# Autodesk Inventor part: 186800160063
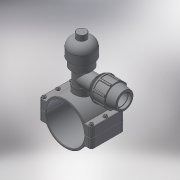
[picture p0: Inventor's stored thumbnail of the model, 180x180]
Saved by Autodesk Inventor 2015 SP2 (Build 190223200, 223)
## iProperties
Created: 2017-05
Part Number: 186800160063
Material: Generic
Description: PLASSON MECHANICAL TAPPING VALVE 160-63
Document SubType Name: Modeling
Designer: KIM
Density: 1 g/cm^3
Appearance: Default
Author: KIM
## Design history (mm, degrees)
derived "18680.ipt"
feature "Solid1::18680.ipt"
feature "Solid2::18680.ipt"
tag "TaggingFeature1"
body "Solid1"
other parameters: "d0" = 176, "d1" = 223, "d4" = 145, "d5" = 0, "d6" = 11.15, "d7" = 223, "d8" = 0.1, "d10" = 0, "d11" = 1.6, "d14" = 73.6528, "d20" = 1.6, "d23" = 1.6, "d36" = 15, "d37" = 12, "d38" = 88, "d39" = 0, "d40" = 3, "d41" = 5, "d42" = 0, "d44" = 3, "d45" = 0, "d46" = 1.6, "d51" = 112, "d52" = 56.656, "d53" = 21, "d54" = 0, "d57" = 0, "d58" = 172.8, "d60" = 0, "d62" = 15, "d63" = 12, "d66" = 121, "d67" = 63, "d68" = 16.66667, "d70" = 113, "d71" = 84.75, "d72" = 2.85714, "d73" = 90.4, "d74" = 120 deg, "d75" = 81.9, "d76" = 10 deg, "d77" = 101.7, "d80" = 50.4, "d82" = 11, "d87" = 28.57143, "d90" = 105.09, "d91" = 35 deg, "d92" = 17.5 deg, "d94" = 0, "d96" = 360 deg, "d98" = 1.26, "d99" = 121, "d100" = 67.8, "d101" = 135 deg, "d102" = 2.26, "d105" = 5.65, "d106" = 0, "d107" = 0.1, "d109" = 73.6528, "d112" = 34.85714, "d113" = 6.66667, "d116" = 0, "d121" = 67.9872, "d122" = 113.312, "d123" = 96.3152, "d124" = 45 deg, "d125" = 219.6, "d126" = 244, "d127" = 146.4, "d128" = 1, "d129" = 65, "G_" = 56.656, "A_" = 112, "L_" = 223, "L_1" = 145, "l_2" = 21, "d_1" = 63, "E_" = 113, "H_1" = 65, "H_2" = 244
